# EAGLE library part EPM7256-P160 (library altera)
EPM7256E MAX 7000 family
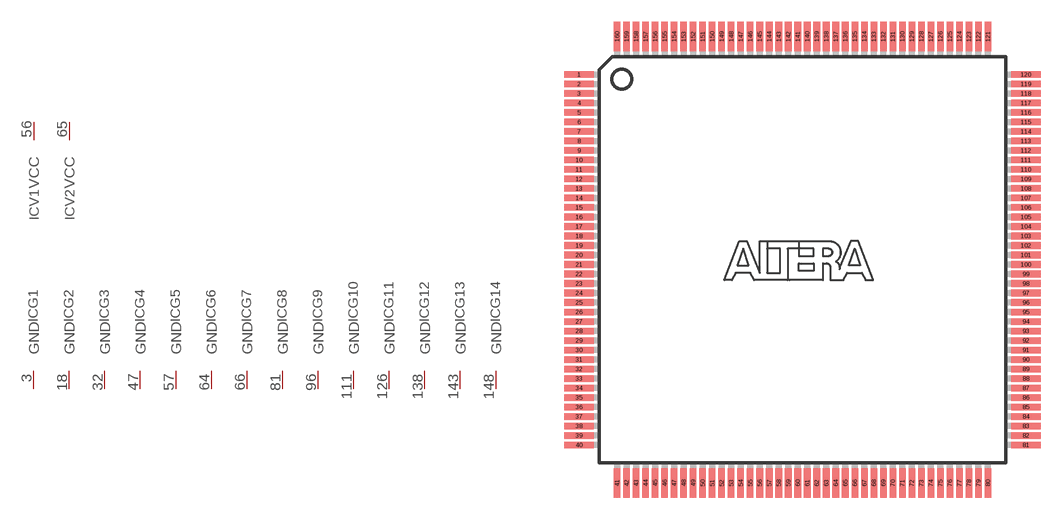
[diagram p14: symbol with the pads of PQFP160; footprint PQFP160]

Designator prefix IC; gates G1=GND G2=GND G3=GND G4=GND G5=GND G6=GND G7=GND G8=GND G9=GND G10=GND G11=GND G12=GND G13=GND G14=GND V1=VCCINT V2=VCCINT V3=VCCINT V4=VCCINT V5=VCCIO V6=VCCIO V7=VCCIO V8=VCCIO V9=VCCIO V10=VCCIO V11=VCCIO V12=VCCIO V13=VCCIO V14=VCCIO _=7256P160

## EPM7256-P160 (MPN: EPM7256EQC160-12; OC_FARNELL: unknown; OC_NEWARK: 51R9894)  [PQFP160]
1  _:IO3
2  _:IO1
3  G1:GND  pwr
4  _:IO32
5  _:IO29
6  _:IO27
7  _:IO25
8  _:IO24
9  _:IO21
10  V5:VCCIO  pwr
11  _:IO19
12  _:IO17
13  _:IO96
14  _:IO93
15  _:IO91
16  _:IO89
17  _:IO88
18  G2:GND  pwr
19  _:IO85
20  _:IO83
21  _:IO81
22  _:IO112
23  _:IO109-TMS
24  _:IO107
25  V6:VCCIO  pwr
26  _:IO105
27  _:IO104
28  _:IO101
29  _:IO99
30  _:IO97
31  _:IO48
32  G3:GND  pwr
33  _:IO45
34  _:IO43
35  _:IO41
36  _:IO40
37  _:IO37
38  _:IO35
39  _:IO33
40  V7:VCCIO  pwr
41  _:IO64
42  _:IO61
43  _:IO59
44  _:IO57
45  _:IO56
46  _:IO53
47  G4:GND  pwr
48  _:IO51
49  _:IO49
50  _:IO128
51  _:IO125
52  _:IO123
53  _:IO121
54  _:IO120
55  V8:VCCIO  pwr
56  V1:VCC  pwr
57  G5:GND  pwr
58  _:IO117
59  _:IO115
60  _:IO113
61  _:IO177
62  _:IO179
63  _:IO181
64  G6:GND  pwr
65  V2:VCC  pwr
66  G7:GND  pwr
67  _:IO184
68  _:IO185
69  _:IO187
70  _:IO189
71  _:IO192
72  _:IO241
73  _:IO243
74  V9:VCCIO  pwr
75  _:IO245
76  _:IO248
77  _:IO249
78  _:IO251
79  _:IO253
80  _:IO256
81  G8:GND  pwr
82  _:IO225
83  _:IO227
84  _:IO229
85  _:IO232
86  _:IO233
87  _:IO235
88  _:IO237
89  V10:VCCIO  pwr
90  _:IO240
91  _:IO161
92  _:IO163
93  _:IO165
94  _:IO168
95  _:IO169
96  G9:GND  pwr
97  _:IO171
98  _:TCK-IO173
99  _:IO176
100  _:IO145
101  _:IO147
102  _:IO149
103  V11:VCCIO  pwr
104  _:IO152
105  _:IO153
106  _:IO155
107  _:IO157
108  _:IO160
109  _:IO209
110  _:IO211
111  G10:GND  pwr
112  _:IO213
113  _:IO216
114  _:IO217
115  _:IO219
116  _:IO221
117  _:IO224
118  V12:VCCIO  pwr
119  _:IO193
120  _:IO195
121  _:IO197
122  _:IO200
123  _:IO201
124  _:IO203
125  _:IO205
126  G11:GND  pwr
127  _:IO208
128  _:IO129
129  _:IO131
130  _:IO133
131  _:IO136
132  _:IO137
133  V13:VCCIO  pwr
134  _:IO139
135  _:TDO-IO141
136  _:IO144
137  V3:VCC  pwr
138  G12:GND  pwr
139  _:GCLK1  in
140  _:OE1  in
141  _:GCLR/  in
142  _:OE2-GCLK2  in
143  G13:GND  pwr
144  V4:VCC  pwr
145  _:IO80
146  _:IO77-TDI
147  _:IO75
148  G14:GND  pwr
149  _:IO73
150  _:IO72
151  _:IO69
152  _:IO67
153  _:IO65
154  _:IO16
155  V14:VCCIO  pwr
156  _:IO13
157  _:IO11
158  _:IO9
159  _:IO8
160  _:IO5

## Footprint PQFP160 (pad centres in mm)
Plastic Quad Flat Pack
smd 2 x 0.45: 1 -15.275,12.675; 2 -15.275,12.025; 3 -15.275,11.375; 4 -15.275,10.725; 5 -15.275,10.075; 6 -15.275,9.425; 7 -15.275,8.775; 8 -15.275,8.125; 9 -15.275,7.475; 10 -15.275,6.825; 11 -15.275,6.175; 12 -15.275,5.525; 13 -15.275,4.875; 14 -15.275,4.225; 15 -15.275,3.575; 16 -15.275,2.925; 17 -15.275,2.275; 18 -15.275,1.625; 19 -15.275,0.975; 20 -15.275,0.325; 21 -15.275,-0.325; 22 -15.275,-0.975; 23 -15.275,-1.625; 24 -15.275,-2.275; 25 -15.275,-2.925; 26 -15.275,-3.575; 27 -15.275,-4.225; 28 -15.275,-4.875; 29 -15.275,-5.525; 30 -15.275,-6.175; 31 -15.275,-6.825; 32 -15.275,-7.475; 33 -15.275,-8.125; 34 -15.275,-8.775; 35 -15.275,-9.425; 36 -15.275,-10.075; 37 -15.275,-10.725; 38 -15.275,-11.375; 39 -15.275,-12.025; 40 -15.275,-12.675; 81 15.275,-12.675; 82 15.275,-12.025; 83 15.275,-11.375; 84 15.275,-10.725; 85 15.275,-10.075; 86 15.275,-9.425; 87 15.275,-8.775; 88 15.275,-8.125; 89 15.275,-7.475; 90 15.275,-6.825; 91 15.275,-6.175; 92 15.275,-5.525; 93 15.275,-4.875; 94 15.275,-4.225; 95 15.275,-3.575; 96 15.275,-2.925; 97 15.275,-2.275; 98 15.275,-1.625; 99 15.275,-0.975; 100 15.275,-0.325; 101 15.275,0.325; 102 15.275,0.975; 103 15.275,1.625; 104 15.275,2.275; 105 15.275,2.925; 106 15.275,3.575; 107 15.275,4.225; 108 15.275,4.875; 109 15.275,5.525; 110 15.275,6.175; 111 15.275,6.825; 112 15.275,7.475; 113 15.275,8.125; 114 15.275,8.775; 115 15.275,9.425; 116 15.275,10.075; 117 15.275,10.725; 118 15.275,11.375; 119 15.275,12.025; 120 15.275,12.675
smd 0.45 x 2: 41 -12.675,-15.275; 42 -12.025,-15.275; 43 -11.375,-15.275; 44 -10.725,-15.275; 45 -10.075,-15.275; 46 -9.425,-15.275; 47 -8.775,-15.275; 48 -8.125,-15.275; 49 -7.475,-15.275; 50 -6.825,-15.275; 51 -6.175,-15.275; 52 -5.525,-15.275; 53 -4.875,-15.275; 54 -4.225,-15.275; 55 -3.575,-15.275; 56 -2.925,-15.275; 57 -2.275,-15.275; 58 -1.625,-15.275; 59 -0.975,-15.275; 60 -0.325,-15.275; 61 0.325,-15.275; 62 0.975,-15.275; 63 1.625,-15.275; 64 2.275,-15.275; 65 2.925,-15.275; 66 3.575,-15.275; 67 4.225,-15.275; 68 4.875,-15.275; 69 5.525,-15.275; 70 6.175,-15.275; 71 6.825,-15.275; 72 7.475,-15.275; 73 8.125,-15.275; 74 8.775,-15.275; 75 9.425,-15.275; 76 10.075,-15.275; 77 10.725,-15.275; 78 11.375,-15.275; 79 12.025,-15.275; 80 12.675,-15.275; 121 12.675,15.275; 122 12.025,15.275; 123 11.375,15.275; 124 10.725,15.275; 125 10.075,15.275; 126 9.425,15.275; 127 8.775,15.275; 128 8.125,15.275; 129 7.475,15.275; 130 6.825,15.275; 131 6.175,15.275; 132 5.525,15.275; 133 4.875,15.275; 134 4.225,15.275; 135 3.575,15.275; 136 2.925,15.275; 137 2.275,15.275; 138 1.625,15.275; 139 0.975,15.275; 140 0.325,15.275; 141 -0.325,15.275; 142 -0.975,15.275; 143 -1.625,15.275; 144 -2.275,15.275; 145 -2.925,15.275; 146 -3.575,15.275; 147 -4.225,15.275; 148 -4.875,15.275; 149 -5.525,15.275; 150 -6.175,15.275; 151 -6.825,15.275; 152 -7.475,15.275; 153 -8.125,15.275; 154 -8.775,15.275; 155 -9.425,15.275; 156 -10.075,15.275; 157 -10.725,15.275; 158 -11.375,15.275; 159 -12.025,15.275; 160 -12.675,15.275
